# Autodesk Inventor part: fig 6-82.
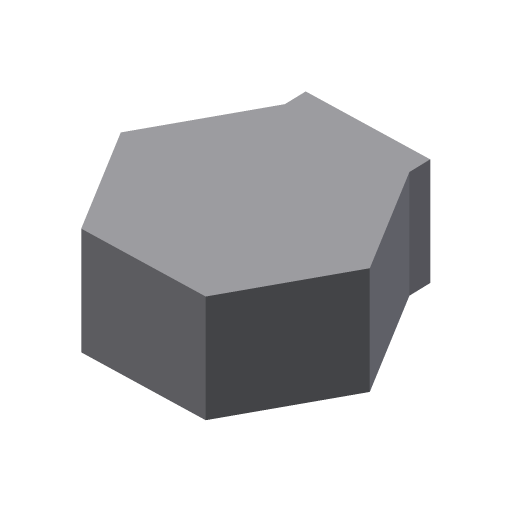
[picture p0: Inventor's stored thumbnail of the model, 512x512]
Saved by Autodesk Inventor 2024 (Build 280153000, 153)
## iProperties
Created: 2009-03
Part Number: fig 6-82.
Document SubType Name: Modeling
Designer: Sham
Density: 1 g/cm^3
Material: Generic
Appearance: Default
Author: Sham
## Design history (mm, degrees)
sketch "Sketch5"
  geometry: L1 (-5.929, 9.627)-(5.372, 9.948); L2 (5.372, 9.948)-(11.301, 0.321); L3 (11.301, 0.321)-(5.929, -9.627); L4 (5.929, -9.627)-(-5.372, -9.948); L5 (-5.372, -9.948)-(-11.301, -0.321); L6 (-11.301, -0.321)-(-5.929, 9.627); 1 further point
  constraints: 12 end point, 13 other
extrude "Extrusion3" new body sketch "Sketch5" distance "d13" = 10; taper "d14" = 0 deg
thicken "Thicken2" dims "d15" = 2, "d16" = 2
body "Solid4"
